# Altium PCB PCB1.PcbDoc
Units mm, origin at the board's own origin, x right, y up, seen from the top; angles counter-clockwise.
Board outline 300 x 100 mm, 2 copper layers (Top Layer, Bottom Layer); 435 components, 0 nets, 870 pads, 0 vias.
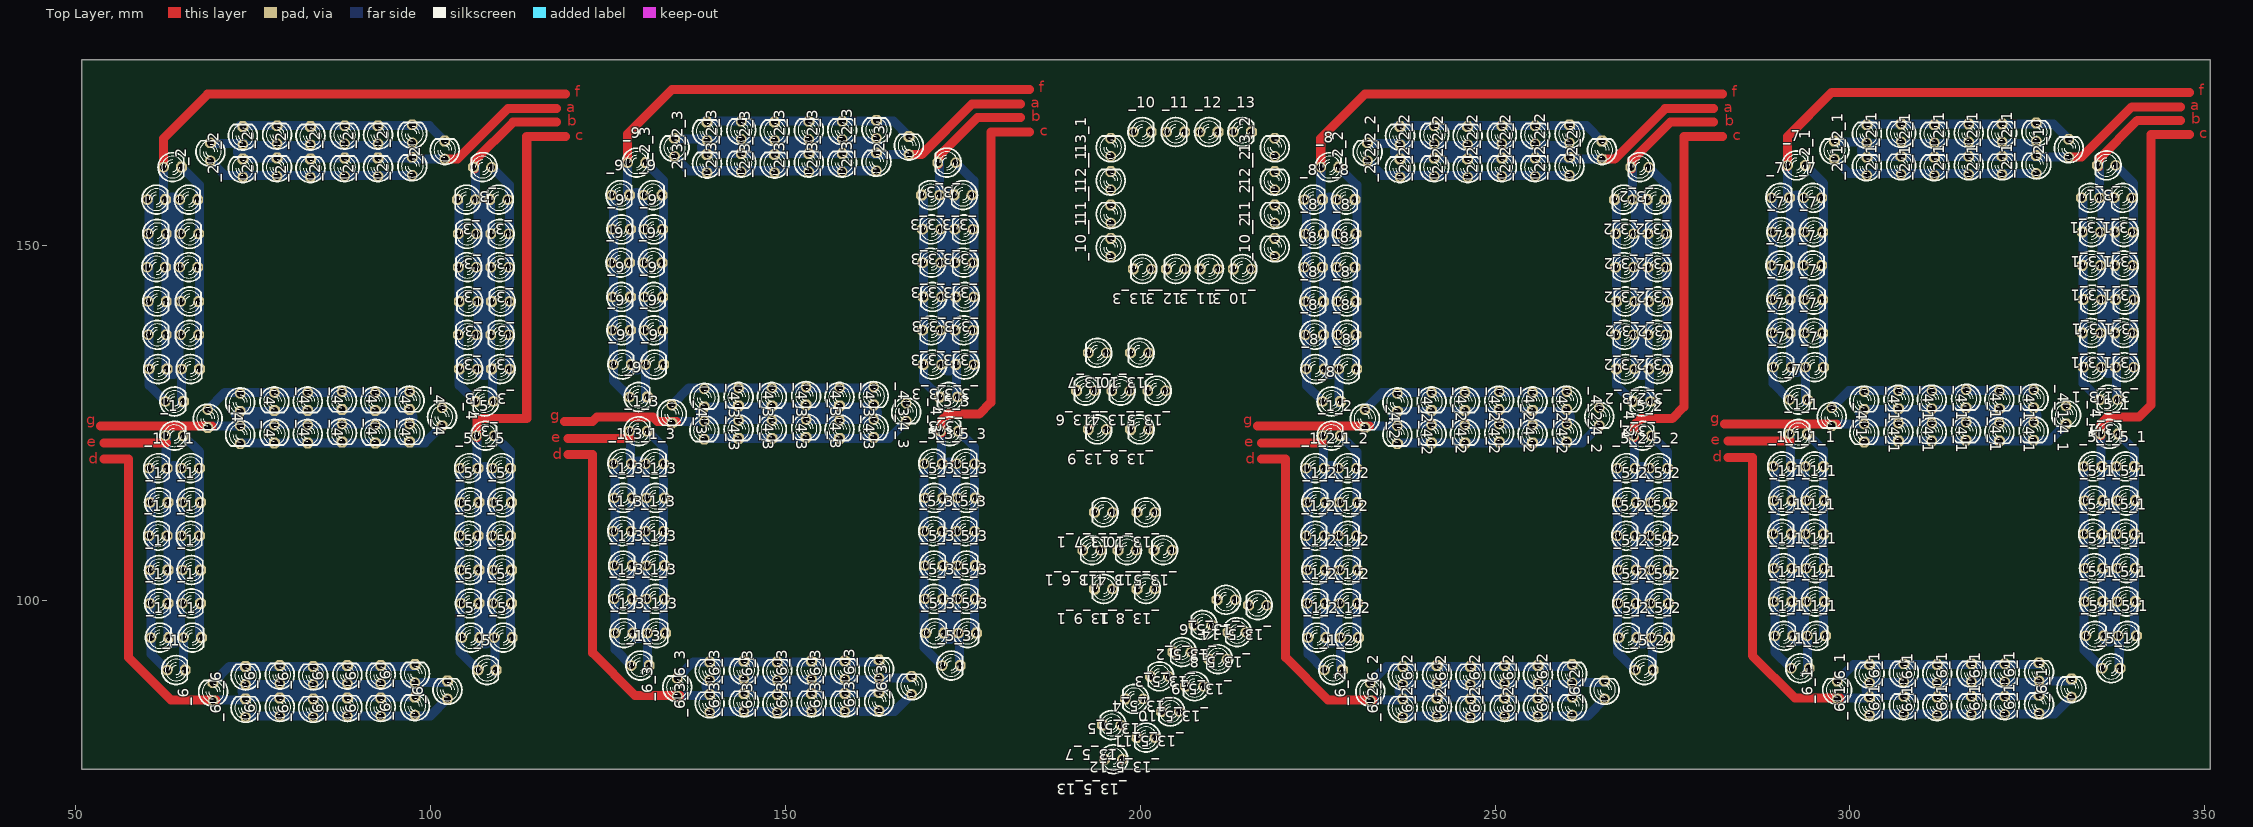
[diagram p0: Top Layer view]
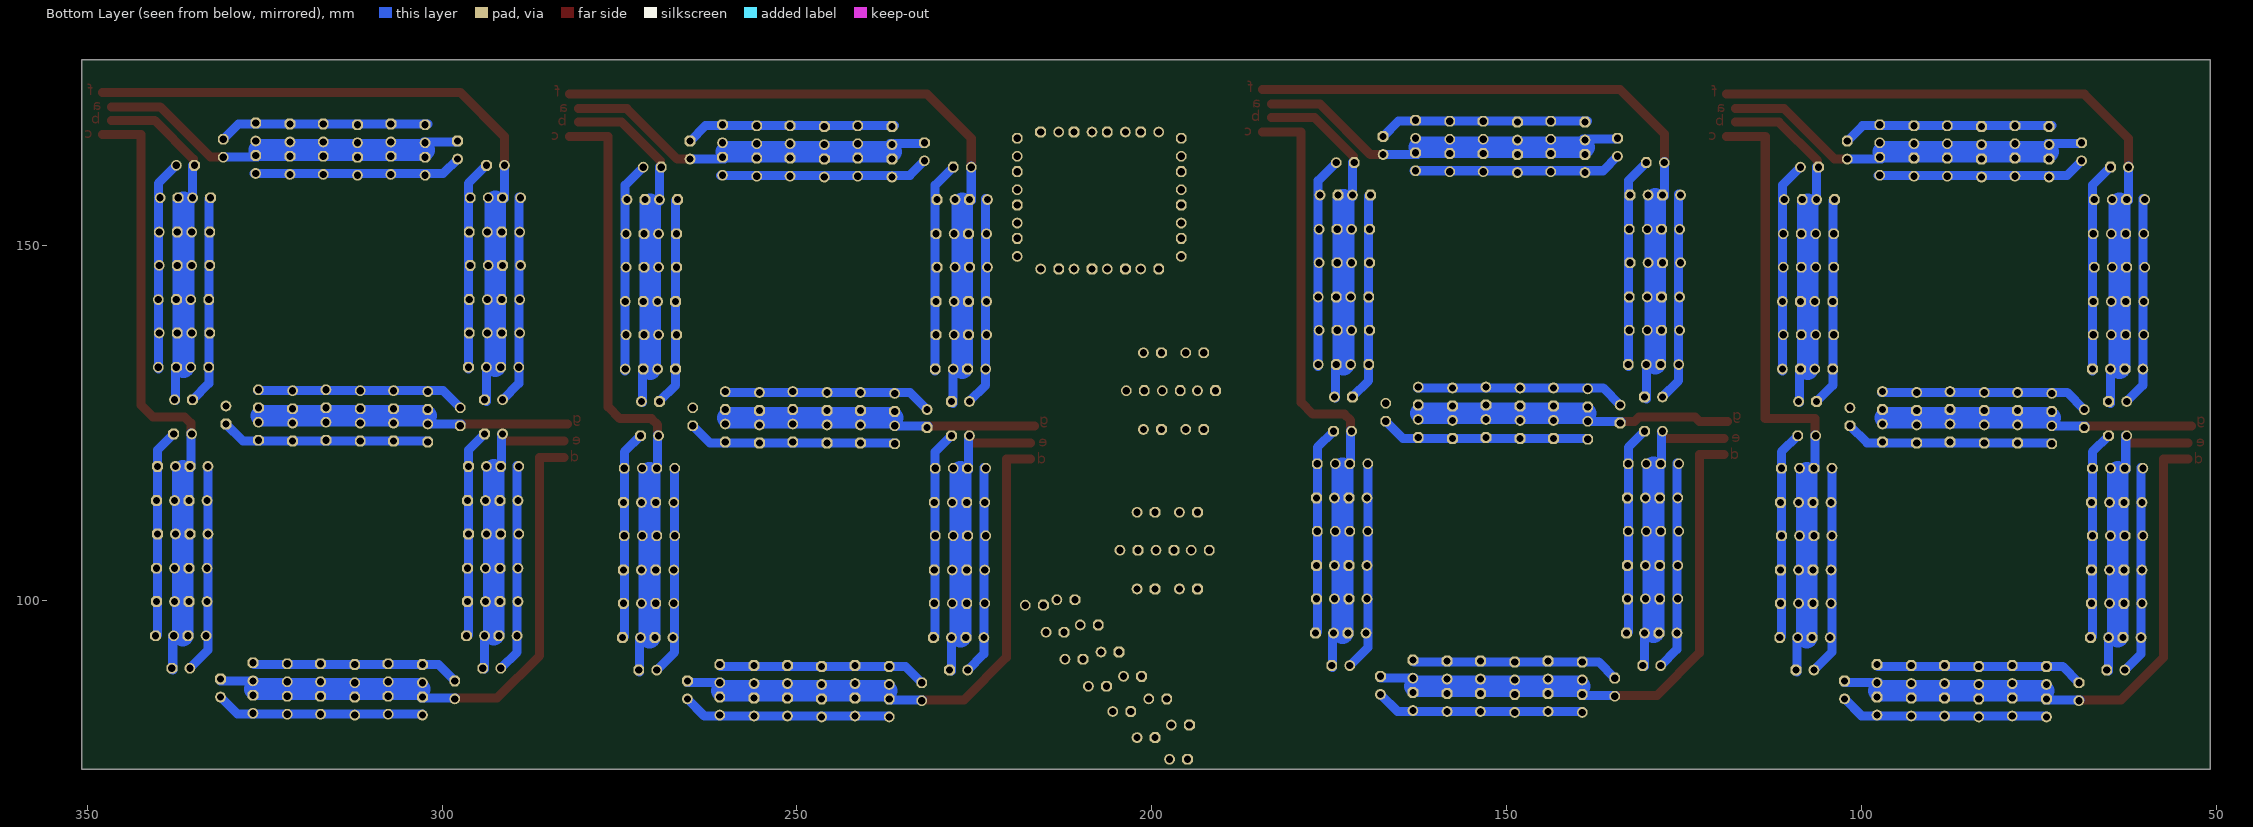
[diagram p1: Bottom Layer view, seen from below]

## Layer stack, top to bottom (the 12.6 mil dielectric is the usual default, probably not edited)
Top Layer: signal copper 0.0356
Dielectric: dielectric 0.32, FR-4, Dk 4.8
Bottom Layer: signal copper 0.0356

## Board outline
50.8,76.2 350.8,76.2 350.8,176.2 50.8,176.2

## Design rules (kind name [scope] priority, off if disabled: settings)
Clearance [All] p1: gap=0.2
PolygonConnect [All] p1: connectstyle=Relief reliefconductorwidth=0.254 reliefentries=4 polygonreliefangle="90 Angle"
RoutingVias [All] p1: holewidth=0.6 width=1 viastyle="Through Hole" minholewidth=0.711 minwidth=1.27 maxholewidth=0.711 maxwidth=1.27
SilkscreenOverComponentPads [All] p1: minsilkscreentomaskgap=0.254
SolderMaskExpansion [All] p1: expansion=0.102
Width [All] p1: maxlimit=0.2 minlimit=0.2 preferedwidth=0.2
27 further rules are at their usual default settings.

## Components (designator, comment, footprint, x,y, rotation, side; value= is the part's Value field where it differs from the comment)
_1 "Comment" My_LED3MM 61.595,118.618 r0 top
_1 "Comment" My_LED3MM 66.167,118.618 r0 top
_1 "Comment" My_LED3MM 61.722,113.792 r0 top
_1 "Comment" My_LED3MM 66.294,113.792 r0 top
_1 "Comment" My_LED3MM 66.294,104.267 r0 top
_1 "Comment" My_LED3MM 61.722,104.267 r0 top
_1 "Comment" My_LED3MM 66.167,109.093 r0 top
_1 "Comment" My_LED3MM 61.595,109.093 r0 top
_1 "Comment" My_LED3MM 66.421,94.742 r0 top
_1 "Comment" My_LED3MM 61.849,94.742 r0 top
_1 "Comment" My_LED3MM 66.294,99.568 r0 top
_1 "Comment" My_LED3MM 61.722,99.568 r0 top
_1 "Comment" My_LED3MM 63.881,123.19 r0 top
_1 "Comment" My_LED3MM 64.135,90.17 r0 top
_1_1 "Comment" My_LED3MM 290.449,118.872 r0 top
_1_1 "Comment" My_LED3MM 295.021,118.872 r0 top
_1_1 "Comment" My_LED3MM 290.576,114.046 r0 top
_1_1 "Comment" My_LED3MM 295.148,114.046 r0 top
_1_1 "Comment" My_LED3MM 295.148,104.521 r0 top
_1_1 "Comment" My_LED3MM 290.576,104.521 r0 top
_1_1 "Comment" My_LED3MM 295.021,109.347 r0 top
_1_1 "Comment" My_LED3MM 290.449,109.347 r0 top
_1_1 "Comment" My_LED3MM 295.275,94.996 r0 top
_1_1 "Comment" My_LED3MM 290.703,94.996 r0 top
_1_1 "Comment" My_LED3MM 295.148,99.822 r0 top
_1_1 "Comment" My_LED3MM 290.576,99.822 r0 top
_1_1 "Comment" My_LED3MM 292.735,123.444 r0 top
_1_1 "Comment" My_LED3MM 292.989,90.424 r0 top
_1_2 "Comment" My_LED3MM 224.663,118.618 r0 top
_1_2 "Comment" My_LED3MM 229.235,118.618 r0 top
_1_2 "Comment" My_LED3MM 224.79,113.792 r0 top
_1_2 "Comment" My_LED3MM 229.362,113.792 r0 top
_1_2 "Comment" My_LED3MM 229.362,104.267 r0 top
_1_2 "Comment" My_LED3MM 224.79,104.267 r0 top
_1_2 "Comment" My_LED3MM 229.235,109.093 r0 top
_1_2 "Comment" My_LED3MM 224.663,109.093 r0 top
_1_2 "Comment" My_LED3MM 229.489,94.742 r0 top
_1_2 "Comment" My_LED3MM 224.917,94.742 r0 top
_1_2 "Comment" My_LED3MM 229.362,99.568 r0 top
_1_2 "Comment" My_LED3MM 224.79,99.568 r0 top
_1_2 "Comment" My_LED3MM 226.949,123.19 r0 top
_1_2 "Comment" My_LED3MM 227.203,90.17 r0 top
_1_3 "Comment" My_LED3MM 127,119.253 r0 top
_1_3 "Comment" My_LED3MM 131.572,119.253 r0 top
_1_3 "Comment" My_LED3MM 127.127,114.427 r0 top
_1_3 "Comment" My_LED3MM 131.699,114.427 r0 top
_1_3 "Comment" My_LED3MM 131.699,104.902 r0 top
_1_3 "Comment" My_LED3MM 127.127,104.902 r0 top
_1_3 "Comment" My_LED3MM 131.572,109.728 r0 top
_1_3 "Comment" My_LED3MM 127,109.728 r0 top
_1_3 "Comment" My_LED3MM 131.826,95.377 r0 top
_1_3 "Comment" My_LED3MM 127.254,95.377 r0 top
_1_3 "Comment" My_LED3MM 131.699,100.203 r0 top
_1_3 "Comment" My_LED3MM 127.127,100.203 r0 top
_1_3 "Comment" My_LED3MM 129.286,123.825 r0 top
_1_3 "Comment" My_LED3MM 129.54,90.805 r0 top
_2 "Comment" My_LED3MM 73.533,160.909 r90 top
_2 "Comment" My_LED3MM 73.533,165.481 r90 top
_2 "Comment" My_LED3MM 78.359,161.036 r90 top
_2 "Comment" My_LED3MM 78.359,165.608 r90 top
_2 "Comment" My_LED3MM 87.884,165.608 r90 top
_2 "Comment" My_LED3MM 87.884,161.036 r90 top
_2 "Comment" My_LED3MM 83.058,165.481 r90 top
_2 "Comment" My_LED3MM 83.058,160.909 r90 top
_2 "Comment" My_LED3MM 97.409,165.735 r90 top
_2 "Comment" My_LED3MM 97.409,161.163 r90 top
_2 "Comment" My_LED3MM 92.583,165.608 r90 top
_2 "Comment" My_LED3MM 92.583,161.036 r90 top
_2 "Comment" My_LED3MM 68.961,163.195 r90 top
_2 "Comment" My_LED3MM 101.981,163.449 r90 top
_2_1 "Comment" My_LED3MM 302.387,161.163 r90 top
_2_1 "Comment" My_LED3MM 302.387,165.735 r90 top
_2_1 "Comment" My_LED3MM 307.213,161.29 r90 top
_2_1 "Comment" My_LED3MM 307.213,165.862 r90 top
_2_1 "Comment" My_LED3MM 316.738,165.862 r90 top
_2_1 "Comment" My_LED3MM 316.738,161.29 r90 top
_2_1 "Comment" My_LED3MM 311.912,165.735 r90 top
_2_1 "Comment" My_LED3MM 311.912,161.163 r90 top
_2_1 "Comment" My_LED3MM 326.263,165.989 r90 top
_2_1 "Comment" My_LED3MM 326.263,161.417 r90 top
_2_1 "Comment" My_LED3MM 321.437,165.862 r90 top
_2_1 "Comment" My_LED3MM 321.437,161.29 r90 top
_2_1 "Comment" My_LED3MM 297.815,163.449 r90 top
_2_1 "Comment" My_LED3MM 330.835,163.703 r90 top
_2_2 "Comment" My_LED3MM 236.601,160.909 r90 top
_2_2 "Comment" My_LED3MM 236.601,165.481 r90 top
_2_2 "Comment" My_LED3MM 241.427,161.036 r90 top
_2_2 "Comment" My_LED3MM 241.427,165.608 r90 top
_2_2 "Comment" My_LED3MM 250.952,165.608 r90 top
_2_2 "Comment" My_LED3MM 250.952,161.036 r90 top
_2_2 "Comment" My_LED3MM 246.126,165.481 r90 top
_2_2 "Comment" My_LED3MM 246.126,160.909 r90 top
_2_2 "Comment" My_LED3MM 260.477,165.735 r90 top
_2_2 "Comment" My_LED3MM 260.477,161.163 r90 top
_2_2 "Comment" My_LED3MM 255.651,165.608 r90 top
_2_2 "Comment" My_LED3MM 255.651,161.036 r90 top
_2_2 "Comment" My_LED3MM 232.029,163.195 r90 top
_2_2 "Comment" My_LED3MM 265.049,163.449 r90 top
_2_3 "Comment" My_LED3MM 138.938,161.544 r90 top
_2_3 "Comment" My_LED3MM 138.938,166.116 r90 top
_2_3 "Comment" My_LED3MM 143.764,161.671 r90 top
_2_3 "Comment" My_LED3MM 143.764,166.243 r90 top
_2_3 "Comment" My_LED3MM 153.289,166.243 r90 top
_2_3 "Comment" My_LED3MM 153.289,161.671 r90 top
_2_3 "Comment" My_LED3MM 148.463,166.116 r90 top
_2_3 "Comment" My_LED3MM 148.463,161.544 r90 top
_2_3 "Comment" My_LED3MM 162.814,166.37 r90 top
_2_3 "Comment" My_LED3MM 162.814,161.798 r90 top
_2_3 "Comment" My_LED3MM 157.988,166.243 r90 top
_2_3 "Comment" My_LED3MM 157.988,161.671 r90 top
_2_3 "Comment" My_LED3MM 134.366,163.83 r90 top
_2_3 "Comment" My_LED3MM 167.386,164.084 r90 top
_3 "Comment" My_LED3MM 109.855,132.588 r180 top
_3 "Comment" My_LED3MM 105.283,132.588 r180 top
_3 "Comment" My_LED3MM 109.728,137.414 r180 top
_3 "Comment" My_LED3MM 105.156,137.414 r180 top
_3 "Comment" My_LED3MM 105.156,146.939 r180 top
_3 "Comment" My_LED3MM 109.728,146.939 r180 top
_3 "Comment" My_LED3MM 105.283,142.113 r180 top
_3 "Comment" My_LED3MM 109.855,142.113 r180 top
_3 "Comment" My_LED3MM 105.029,156.464 r180 top
_3 "Comment" My_LED3MM 109.601,156.464 r180 top
_3 "Comment" My_LED3MM 105.156,151.638 r180 top
_3 "Comment" My_LED3MM 109.728,151.638 r180 top
_3 "Comment" My_LED3MM 107.569,128.016 r180 top
_3 "Comment" My_LED3MM 107.315,161.036 r180 top
_3_1 "Comment" My_LED3MM 338.709,132.842 r180 top
_3_1 "Comment" My_LED3MM 334.137,132.842 r180 top
_3_1 "Comment" My_LED3MM 338.582,137.668 r180 top
_3_1 "Comment" My_LED3MM 334.01,137.668 r180 top
_3_1 "Comment" My_LED3MM 334.01,147.193 r180 top
_3_1 "Comment" My_LED3MM 338.582,147.193 r180 top
_3_1 "Comment" My_LED3MM 334.137,142.367 r180 top
_3_1 "Comment" My_LED3MM 338.709,142.367 r180 top
_3_1 "Comment" My_LED3MM 333.883,156.718 r180 top
_3_1 "Comment" My_LED3MM 338.455,156.718 r180 top
_3_1 "Comment" My_LED3MM 334.01,151.892 r180 top
_3_1 "Comment" My_LED3MM 338.582,151.892 r180 top
_3_1 "Comment" My_LED3MM 336.423,128.27 r180 top
_3_1 "Comment" My_LED3MM 336.169,161.29 r180 top
_3_2 "Comment" My_LED3MM 272.923,132.588 r180 top
_3_2 "Comment" My_LED3MM 268.351,132.588 r180 top
_3_2 "Comment" My_LED3MM 272.796,137.414 r180 top
_3_2 "Comment" My_LED3MM 268.224,137.414 r180 top
_3_2 "Comment" My_LED3MM 268.224,146.939 r180 top
_3_2 "Comment" My_LED3MM 272.796,146.939 r180 top
_3_2 "Comment" My_LED3MM 268.351,142.113 r180 top
_3_2 "Comment" My_LED3MM 272.923,142.113 r180 top
_3_2 "Comment" My_LED3MM 268.097,156.464 r180 top
_3_2 "Comment" My_LED3MM 272.669,156.464 r180 top
_3_2 "Comment" My_LED3MM 268.224,151.638 r180 top
_3_2 "Comment" My_LED3MM 272.796,151.638 r180 top
_3_2 "Comment" My_LED3MM 270.637,128.016 r180 top
_3_2 "Comment" My_LED3MM 270.383,161.036 r180 top
_3_3 "Comment" My_LED3MM 175.26,133.223 r180 top
_3_3 "Comment" My_LED3MM 170.688,133.223 r180 top
_3_3 "Comment" My_LED3MM 175.133,138.049 r180 top
_3_3 "Comment" My_LED3MM 170.561,138.049 r180 top
_3_3 "Comment" My_LED3MM 170.561,147.574 r180 top
_3_3 "Comment" My_LED3MM 175.133,147.574 r180 top
_3_3 "Comment" My_LED3MM 170.688,142.748 r180 top
_3_3 "Comment" My_LED3MM 175.26,142.748 r180 top
_3_3 "Comment" My_LED3MM 170.434,157.099 r180 top
_3_3 "Comment" My_LED3MM 175.006,157.099 r180 top
_3_3 "Comment" My_LED3MM 170.561,152.273 r180 top
_3_3 "Comment" My_LED3MM 175.133,152.273 r180 top
_3_3 "Comment" My_LED3MM 172.974,128.651 r180 top
_3_3 "Comment" My_LED3MM 172.72,161.671 r180 top
_4 "Comment" My_LED3MM 97.028,128.143 r270 top
_4 "Comment" My_LED3MM 97.028,123.571 r270 top
_4 "Comment" My_LED3MM 92.202,128.016 r270 top
_4 "Comment" My_LED3MM 92.202,123.444 r270 top
_4 "Comment" My_LED3MM 82.677,123.444 r270 top
_4 "Comment" My_LED3MM 82.677,128.016 r270 top
_4 "Comment" My_LED3MM 87.503,123.571 r270 top
_4 "Comment" My_LED3MM 87.503,128.143 r270 top
_4 "Comment" My_LED3MM 73.152,123.317 r270 top
_4 "Comment" My_LED3MM 73.152,127.889 r270 top
_4 "Comment" My_LED3MM 77.978,123.444 r270 top
_4 "Comment" My_LED3MM 77.978,128.016 r270 top
_4 "Comment" My_LED3MM 101.6,125.857 r270 top
_4 "Comment" My_LED3MM 68.58,125.603 r270 top
_4_1 "Comment" My_LED3MM 325.882,128.397 r270 top
_4_1 "Comment" My_LED3MM 325.882,123.825 r270 top
_4_1 "Comment" My_LED3MM 321.056,128.27 r270 top
_4_1 "Comment" My_LED3MM 321.056,123.698 r270 top
_4_1 "Comment" My_LED3MM 311.531,123.698 r270 top
_4_1 "Comment" My_LED3MM 311.531,128.27 r270 top
_4_1 "Comment" My_LED3MM 316.357,123.825 r270 top
_4_1 "Comment" My_LED3MM 316.357,128.397 r270 top
_4_1 "Comment" My_LED3MM 302.006,123.571 r270 top
_4_1 "Comment" My_LED3MM 302.006,128.143 r270 top
_4_1 "Comment" My_LED3MM 306.832,123.698 r270 top
_4_1 "Comment" My_LED3MM 306.832,128.27 r270 top
_4_1 "Comment" My_LED3MM 330.454,126.111 r270 top
_4_1 "Comment" My_LED3MM 297.434,125.857 r270 top
_4_2 "Comment" My_LED3MM 260.096,128.143 r270 top
_4_2 "Comment" My_LED3MM 260.096,123.571 r270 top
_4_2 "Comment" My_LED3MM 255.27,128.016 r270 top
_4_2 "Comment" My_LED3MM 255.27,123.444 r270 top
_4_2 "Comment" My_LED3MM 245.745,123.444 r270 top
_4_2 "Comment" My_LED3MM 245.745,128.016 r270 top
_4_2 "Comment" My_LED3MM 250.571,123.571 r270 top
_4_2 "Comment" My_LED3MM 250.571,128.143 r270 top
_4_2 "Comment" My_LED3MM 236.22,123.317 r270 top
_4_2 "Comment" My_LED3MM 236.22,127.889 r270 top
_4_2 "Comment" My_LED3MM 241.046,123.444 r270 top
_4_2 "Comment" My_LED3MM 241.046,128.016 r270 top
_4_2 "Comment" My_LED3MM 264.668,125.857 r270 top
_4_2 "Comment" My_LED3MM 231.648,125.603 r270 top
_4_3 "Comment" My_LED3MM 162.433,128.778 r270 top
_4_3 "Comment" My_LED3MM 162.433,124.206 r270 top
_4_3 "Comment" My_LED3MM 157.607,128.651 r270 top
_4_3 "Comment" My_LED3MM 157.607,124.079 r270 top
_4_3 "Comment" My_LED3MM 148.082,124.079 r270 top
_4_3 "Comment" My_LED3MM 148.082,128.651 r270 top
_4_3 "Comment" My_LED3MM 152.908,124.206 r270 top
_4_3 "Comment" My_LED3MM 152.908,128.778 r270 top
_4_3 "Comment" My_LED3MM 138.557,123.952 r270 top
_4_3 "Comment" My_LED3MM 138.557,128.524 r270 top
_4_3 "Comment" My_LED3MM 143.383,124.079 r270 top
_4_3 "Comment" My_LED3MM 143.383,128.651 r270 top
_4_3 "Comment" My_LED3MM 167.005,126.492 r270 top
_4_3 "Comment" My_LED3MM 133.985,126.238 r270 top
_5 "Comment" My_LED3MM 105.41,118.618 r0 top
_5 "Comment" My_LED3MM 109.982,118.618 r0 top
_5 "Comment" My_LED3MM 105.537,113.792 r0 top
_5 "Comment" My_LED3MM 110.109,113.792 r0 top
_5 "Comment" My_LED3MM 110.109,104.267 r0 top
_5 "Comment" My_LED3MM 105.537,104.267 r0 top
_5 "Comment" My_LED3MM 109.982,109.093 r0 top
_5 "Comment" My_LED3MM 105.41,109.093 r0 top
_5 "Comment" My_LED3MM 110.236,94.742 r0 top
_5 "Comment" My_LED3MM 105.664,94.742 r0 top
_5 "Comment" My_LED3MM 110.109,99.568 r0 top
_5 "Comment" My_LED3MM 105.537,99.568 r0 top
_5 "Comment" My_LED3MM 107.696,123.19 r0 top
_5 "Comment" My_LED3MM 107.95,90.17 r0 top
_5_1 "Comment" My_LED3MM 334.264,118.872 r0 top
_5_1 "Comment" My_LED3MM 338.836,118.872 r0 top
_5_1 "Comment" My_LED3MM 334.391,114.046 r0 top
_5_1 "Comment" My_LED3MM 338.963,114.046 r0 top
_5_1 "Comment" My_LED3MM 338.963,104.521 r0 top
_5_1 "Comment" My_LED3MM 334.391,104.521 r0 top
_5_1 "Comment" My_LED3MM 338.836,109.347 r0 top
_5_1 "Comment" My_LED3MM 334.264,109.347 r0 top
_5_1 "Comment" My_LED3MM 339.09,94.996 r0 top
_5_1 "Comment" My_LED3MM 334.518,94.996 r0 top
_5_1 "Comment" My_LED3MM 338.963,99.822 r0 top
_5_1 "Comment" My_LED3MM 334.391,99.822 r0 top
_5_1 "Comment" My_LED3MM 336.55,123.444 r0 top
_5_1 "Comment" My_LED3MM 336.804,90.424 r0 top
_5_2 "Comment" My_LED3MM 268.478,118.618 r0 top
_5_2 "Comment" My_LED3MM 273.05,118.618 r0 top
_5_2 "Comment" My_LED3MM 268.605,113.792 r0 top
_5_2 "Comment" My_LED3MM 273.177,113.792 r0 top
_5_2 "Comment" My_LED3MM 273.177,104.267 r0 top
_5_2 "Comment" My_LED3MM 268.605,104.267 r0 top
_5_2 "Comment" My_LED3MM 273.05,109.093 r0 top
_5_2 "Comment" My_LED3MM 268.478,109.093 r0 top
_5_2 "Comment" My_LED3MM 273.304,94.742 r0 top
_5_2 "Comment" My_LED3MM 268.732,94.742 r0 top
_5_2 "Comment" My_LED3MM 273.177,99.568 r0 top
_5_2 "Comment" My_LED3MM 268.605,99.568 r0 top
_5_2 "Comment" My_LED3MM 270.764,123.19 r0 top
_5_2 "Comment" My_LED3MM 271.018,90.17 r0 top
_5_3 "Comment" My_LED3MM 170.815,119.253 r0 top
_5_3 "Comment" My_LED3MM 175.387,119.253 r0 top
_5_3 "Comment" My_LED3MM 170.942,114.427 r0 top
_5_3 "Comment" My_LED3MM 175.514,114.427 r0 top
_5_3 "Comment" My_LED3MM 175.514,104.902 r0 top
_5_3 "Comment" My_LED3MM 170.942,104.902 r0 top
_5_3 "Comment" My_LED3MM 175.387,109.728 r0 top
_5_3 "Comment" My_LED3MM 170.815,109.728 r0 top
_5_3 "Comment" My_LED3MM 175.641,95.377 r0 top
_5_3 "Comment" My_LED3MM 171.069,95.377 r0 top
_5_3 "Comment" My_LED3MM 175.514,100.203 r0 top
_5_3 "Comment" My_LED3MM 170.942,100.203 r0 top
_5_3 "Comment" My_LED3MM 173.101,123.825 r0 top
_5_3 "Comment" My_LED3MM 173.355,90.805 r0 top
_6 "Comment" My_LED3MM 73.914,84.836 r90 top
_6 "Comment" My_LED3MM 73.914,89.408 r90 top
_6 "Comment" My_LED3MM 78.74,84.963 r90 top
_6 "Comment" My_LED3MM 78.74,89.535 r90 top
_6 "Comment" My_LED3MM 88.265,89.535 r90 top
_6 "Comment" My_LED3MM 88.265,84.963 r90 top
_6 "Comment" My_LED3MM 83.439,89.408 r90 top
_6 "Comment" My_LED3MM 83.439,84.836 r90 top
_6 "Comment" My_LED3MM 97.79,89.662 r90 top
_6 "Comment" My_LED3MM 97.79,85.09 r90 top
_6 "Comment" My_LED3MM 92.964,89.535 r90 top
_6 "Comment" My_LED3MM 92.964,84.963 r90 top
_6 "Comment" My_LED3MM 69.342,87.122 r90 top
_6 "Comment" My_LED3MM 102.362,87.376 r90 top
_6_1 "Comment" My_LED3MM 302.768,85.09 r90 top
_6_1 "Comment" My_LED3MM 302.768,89.662 r90 top
_6_1 "Comment" My_LED3MM 307.594,85.217 r90 top
_6_1 "Comment" My_LED3MM 307.594,89.789 r90 top
_6_1 "Comment" My_LED3MM 317.119,89.789 r90 top
_6_1 "Comment" My_LED3MM 317.119,85.217 r90 top
_6_1 "Comment" My_LED3MM 312.293,89.662 r90 top
_6_1 "Comment" My_LED3MM 312.293,85.09 r90 top
_6_1 "Comment" My_LED3MM 326.644,89.916 r90 top
_6_1 "Comment" My_LED3MM 326.644,85.344 r90 top
_6_1 "Comment" My_LED3MM 321.818,89.789 r90 top
_6_1 "Comment" My_LED3MM 321.818,85.217 r90 top
_6_1 "Comment" My_LED3MM 298.196,87.376 r90 top
_6_1 "Comment" My_LED3MM 331.216,87.63 r90 top
_6_2 "Comment" My_LED3MM 236.982,84.836 r90 top
_6_2 "Comment" My_LED3MM 236.982,89.408 r90 top
_6_2 "Comment" My_LED3MM 241.808,84.963 r90 top
_6_2 "Comment" My_LED3MM 241.808,89.535 r90 top
_6_2 "Comment" My_LED3MM 251.333,89.535 r90 top
_6_2 "Comment" My_LED3MM 251.333,84.963 r90 top
_6_2 "Comment" My_LED3MM 246.507,89.408 r90 top
_6_2 "Comment" My_LED3MM 246.507,84.836 r90 top
_6_2 "Comment" My_LED3MM 260.858,89.662 r90 top
_6_2 "Comment" My_LED3MM 260.858,85.09 r90 top
_6_2 "Comment" My_LED3MM 256.032,89.535 r90 top
_6_2 "Comment" My_LED3MM 256.032,84.963 r90 top
_6_2 "Comment" My_LED3MM 232.41,87.122 r90 top
_6_2 "Comment" My_LED3MM 265.43,87.376 r90 top
_6_3 "Comment" My_LED3MM 139.319,85.471 r90 top
_6_3 "Comment" My_LED3MM 139.319,90.043 r90 top
_6_3 "Comment" My_LED3MM 144.145,85.598 r90 top
_6_3 "Comment" My_LED3MM 144.145,90.17 r90 top
_6_3 "Comment" My_LED3MM 153.67,90.17 r90 top
_6_3 "Comment" My_LED3MM 153.67,85.598 r90 top
_6_3 "Comment" My_LED3MM 148.844,90.043 r90 top
_6_3 "Comment" My_LED3MM 148.844,85.471 r90 top
_6_3 "Comment" My_LED3MM 163.195,90.297 r90 top
_6_3 "Comment" My_LED3MM 163.195,85.725 r90 top
_6_3 "Comment" My_LED3MM 158.369,90.17 r90 top
_6_3 "Comment" My_LED3MM 158.369,85.598 r90 top
_6_3 "Comment" My_LED3MM 134.747,87.757 r90 top
_6_3 "Comment" My_LED3MM 167.767,88.011 r90 top
_7 "Comment" My_LED3MM 292.735,128.27 r0 top
_7 "Comment" My_LED3MM 292.481,161.29 r0 top
_7 "Comment" My_LED3MM 290.322,137.668 r0 top
_7 "Comment" My_LED3MM 294.894,137.668 r0 top
_7 "Comment" My_LED3MM 290.449,132.842 r0 top
_7 "Comment" My_LED3MM 295.021,132.842 r0 top
_7 "Comment" My_LED3MM 290.195,147.193 r0 top
_7 "Comment" My_LED3MM 294.767,147.193 r0 top
_7 "Comment" My_LED3MM 290.322,142.367 r0 top
_7 "Comment" My_LED3MM 294.894,142.367 r0 top
_7 "Comment" My_LED3MM 294.894,151.892 r0 top
_7 "Comment" My_LED3MM 290.322,151.892 r0 top
_7 "Comment" My_LED3MM 294.767,156.718 r0 top
_7 "Comment" My_LED3MM 290.195,156.718 r0 top
_8 "Comment" My_LED3MM 226.949,128.016 r0 top
_8 "Comment" My_LED3MM 226.695,161.036 r0 top
_8 "Comment" My_LED3MM 224.536,137.414 r0 top
_8 "Comment" My_LED3MM 229.108,137.414 r0 top
_8 "Comment" My_LED3MM 224.663,132.588 r0 top
_8 "Comment" My_LED3MM 229.235,132.588 r0 top
_8 "Comment" My_LED3MM 224.409,146.939 r0 top
_8 "Comment" My_LED3MM 228.981,146.939 r0 top
_8 "Comment" My_LED3MM 224.536,142.113 r0 top
_8 "Comment" My_LED3MM 229.108,142.113 r0 top
_8 "Comment" My_LED3MM 229.108,151.638 r0 top
_8 "Comment" My_LED3MM 224.536,151.638 r0 top
_8 "Comment" My_LED3MM 228.981,156.464 r0 top
_8 "Comment" My_LED3MM 224.409,156.464 r0 top
_9 "Comment" My_LED3MM 129.286,128.651 r0 top
_9 "Comment" My_LED3MM 129.032,161.671 r0 top
_9 "Comment" My_LED3MM 126.873,138.049 r0 top
_9 "Comment" My_LED3MM 131.445,138.049 r0 top
_9 "Comment" My_LED3MM 127,133.223 r0 top
_9 "Comment" My_LED3MM 131.572,133.223 r0 top
_9 "Comment" My_LED3MM 126.746,147.574 r0 top
_9 "Comment" My_LED3MM 131.318,147.574 r0 top
_9 "Comment" My_LED3MM 126.873,142.748 r0 top
_9 "Comment" My_LED3MM 131.445,142.748 r0 top
_9 "Comment" My_LED3MM 131.445,152.273 r0 top
_9 "Comment" My_LED3MM 126.873,152.273 r0 top
_9 "Comment" My_LED3MM 131.318,157.099 r0 top
_9 "Comment" My_LED3MM 126.746,157.099 r0 top
_10 "Comment" My_LED3MM 200.279,165.989 r0 top
_10_1 "Comment" My_LED3MM 195.834,149.733 r90 top
_10_2 "Comment" My_LED3MM 218.948,149.733 r90 top
_10_3 "Comment" My_LED3MM 214.376,146.685 r180 top
_11 "Comment" My_LED3MM 204.978,165.989 r0 top
_11_1 "Comment" My_LED3MM 195.834,154.432 r90 top
_11_2 "Comment" My_LED3MM 218.948,154.432 r90 top
_11_3 "Comment" My_LED3MM 209.677,146.685 r180 top
_12 "Comment" My_LED3MM 209.677,165.989 r0 top
_12_1 "Comment" My_LED3MM 195.834,159.131 r90 top
_12_2 "Comment" My_LED3MM 218.948,159.131 r90 top
_12_3 "Comment" My_LED3MM 204.978,146.685 r180 top
_13 "Comment" My_LED3MM 214.376,165.989 r0 top
_13_1 "Comment" My_LED3MM 195.834,163.83 r90 top
_13_2 "Comment" My_LED3MM 218.948,163.83 r90 top
_13_3 "Comment" My_LED3MM 200.279,146.685 r180 top
_13_4 "Comment" My_LED3MM 197.231,129.54 r180 top
_13_4_1 "Comment" My_LED3MM 198.12,107.061 r180 top
_13_5 "Comment" My_LED3MM 202.311,129.54 r180 top
_13_5_1 "Comment" My_LED3MM 203.2,107.061 r180 top
_13_5_2 "Comment" My_LED3MM 208.788,96.52 r180 top
_13_5_3 "Comment" My_LED3MM 205.867,92.71 r180 top
_13_5_4 "Comment" My_LED3MM 202.692,89.281 r180 top
_13_5_5 "Comment" My_LED3MM 199.136,86.106 r180 top
_13_5_6 "Comment" My_LED3MM 212.09,100.076 r180 top
_13_5_7 "Comment" My_LED3MM 195.961,82.423 r180 top
_13_5_8 "Comment" My_LED3MM 213.614,95.504 r180 top
_13_5_9 "Comment" My_LED3MM 210.947,91.694 r180 top
_13_5_10 "Comment" My_LED3MM 207.645,87.884 r180 top
_13_5_11 "Comment" My_LED3MM 204.216,84.328 r180 top
_13_5_12 "Comment" My_LED3MM 200.787,80.645 r180 top
_13_5_13 "Comment" My_LED3MM 196.215,77.597 r180 top
_13_5_14 "Comment" My_LED3MM 216.535,99.314 r180 top
_13_6 "Comment" My_LED3MM 192.278,129.54 r180 top
_13_6_1 "Comment" My_LED3MM 193.167,107.061 r180 top
_13_7 "Comment" My_LED3MM 193.929,134.874 r180 top
_13_7_1 "Comment" My_LED3MM 194.818,112.395 r180 top
_13_8 "Comment" My_LED3MM 199.898,124.079 r180 top
_13_8_1 "Comment" My_LED3MM 200.787,101.6 r180 top
_13_9 "Comment" My_LED3MM 193.929,124.079 r180 top
_13_9_1 "Comment" My_LED3MM 194.818,101.6 r180 top
_13_10 "Comment" My_LED3MM 199.898,134.874 r180 top
_13_10_1 "Comment" My_LED3MM 200.787,112.395 r180 top
? "Comment" My_LED3MM 63.881,128.016 r0 top
? "Comment" My_LED3MM 63.627,161.036 r0 top
? "Comment" My_LED3MM 61.468,137.414 r0 top
? "Comment" My_LED3MM 66.04,137.414 r0 top
? "Comment" My_LED3MM 61.595,132.588 r0 top
? "Comment" My_LED3MM 66.167,132.588 r0 top
? "Comment" My_LED3MM 61.341,146.939 r0 top
? "Comment" My_LED3MM 65.913,146.939 r0 top
? "Comment" My_LED3MM 61.468,142.113 r0 top
? "Comment" My_LED3MM 66.04,142.113 r0 top
? "Comment" My_LED3MM 66.04,151.638 r0 top
? "Comment" My_LED3MM 61.468,151.638 r0 top
? "Comment" My_LED3MM 65.913,156.464 r0 top
? "Comment" My_LED3MM 61.341,156.464 r0 top

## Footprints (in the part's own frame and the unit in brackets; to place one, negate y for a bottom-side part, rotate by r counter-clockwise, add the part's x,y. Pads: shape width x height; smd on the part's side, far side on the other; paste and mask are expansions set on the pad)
My_LED3MM [mil]
  round 60 hole 40: A(-50,0)
  oct 60x60 hole 40: K(50,0)
  silkscreen extent -80,-80 62,80

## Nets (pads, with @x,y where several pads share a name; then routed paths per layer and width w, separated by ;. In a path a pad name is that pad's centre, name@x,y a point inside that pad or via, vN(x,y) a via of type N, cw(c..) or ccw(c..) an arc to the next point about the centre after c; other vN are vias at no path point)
pads on no net: ?.A ?.K _1.A _1.K _1_1.A _1_1.K _1_2.A _1_2.K _1_3.A _1_3.K _2.A _2.K _2_1.A _2_1.K _2_2.A _2_2.K _2_3.A _2_3.K _3.A _3.K _3_1.A _3_1.K _3_2.A _3_2.K _3_3.A _3_3.K _4.A _4.K _4_1.A _4_1.K _4_2.A _4_2.K _4_3.A _4_3.K _5.A _5.K _5_1.A _5_1.K _5_2.A _5_2.K _5_3.A _5_3.K _6.A _6.K _6_1.A _6_1.K _6_2.A _6_2.K _6_3.A _6_3.K _7.A _7.K _8.A _8.K _9.A _9.K _10.A _10.K _10_1.A _10_1.K _10_2.A _10_2.K _10_3.A _10_3.K _11.A _11.K _11_1.A _11_1.K _11_2.A _11_2.K _11_3.A _11_3.K _12.A _12.K _12_1.A _12_1.K _12_2.A _12_2.K _12_3.A _12_3.K _13.A _13.K _13_1.A _13_1.K _13_2.A _13_2.K _13_3.A _13_3.K _13_4.A _13_4.K _13_4_1.A _13_4_1.K _13_5.A _13_5.K _13_5_1.A _13_5_1.K _13_5_2.A _13_5_2.K _13_5_3.A _13_5_3.K _13_5_4.A _13_5_4.K _13_5_5.A _13_5_5.K _13_5_6.A _13_5_6.K _13_5_7.A _13_5_7.K _13_5_8.A _13_5_8.K _13_5_9.A _13_5_9.K _13_5_10.A _13_5_10.K _13_5_11.A _13_5_11.K _13_5_12.A _13_5_12.K _13_5_13.A _13_5_13.K _13_5_14.A _13_5_14.K _13_6.A _13_6.K _13_6_1.A _13_6_1.K _13_7.A _13_7.K _13_7_1.A _13_7_1.K _13_8.A _13_8.K _13_8_1.A _13_8_1.K _13_9.A _13_9.K _13_9_1.A _13_9_1.K _13_10.A _13_10.K _13_10_1.A _13_10_1.K
copper on no net: | length 3440.6
  Top Layer w1.27: 53.467,124.587 69.215,124.587 ; 53.975,119.888 57.404,119.888 57.404,91.948 63.373,85.979 69.723,85.979 ; 53.975,122.174 62.738,122.174 ; 62.357,160.909 62.357,165.1 68.58,171.323 118.999,171.323 ; 101.981,162.179 103.759,162.179 110.871,169.291 117.729,169.291 ; 106.172,160.782 106.172,161.925 111.633,167.386 117.729,167.386 ; 106.553,122.936 106.553,125.603 113.538,125.603 113.538,165.354 118.999,165.354 ; 118.872,125.222 122.809,125.222 123.444,125.857 130.048,125.857 131.318,125.857 131.953,125.222 134.62,125.222 ; 119.38,120.523 122.809,120.523 122.809,92.583 128.778,86.614 135.128,86.614 ; 119.38,122.809 128.143,122.809 ; 127.762,161.544 127.762,165.735 133.985,171.958 184.404,171.958 ; 167.386,162.814 169.164,162.814 176.276,169.926 183.134,169.926 ; 171.577,161.417 171.577,162.56 177.038,168.021 183.134,168.021 ; 171.958,123.571 171.958,125.349 172.847,126.238 177.292,126.238 178.943,127.889 178.943,165.989 184.404,165.989 ; 216.535,124.587 232.283,124.587 ; 217.043,119.888 220.472,119.888 220.472,91.948 226.441,85.979 232.791,85.979 ; 217.043,122.174 225.806,122.174 ; 225.425,160.909 225.425,165.1 231.648,171.323 282.067,171.323 ; 265.049,162.179 266.827,162.179 273.939,169.291 280.797,169.291 ; 269.24,160.782 269.24,161.925 274.701,167.386 280.797,167.386 ; 269.621,122.936 269.621,124.714 270.51,125.603 274.955,125.603 276.606,127.254 276.606,165.354 282.067,165.354 ; 282.321,124.841 298.069,124.841 ; 282.829,120.142 286.258,120.142 286.258,92.202 292.227,86.233 298.577,86.233 ; 282.829,122.428 291.592,122.428 ; 291.211,161.163 291.211,165.354 297.434,171.577 347.853,171.577 ; 330.835,162.433 332.613,162.433 339.725,169.545 346.583,169.545 ; 335.026,161.036 335.026,162.179 340.487,167.64 346.583,167.64 ; 335.407,123.19 335.407,124.968 336.296,125.857 340.741,125.857 342.392,127.508 342.392,165.608 347.853,165.608
  Bottom Layer w1.27: 60.325,156.591 60.325,130.302 62.611,128.016 ; 60.579,118.745 60.579,92.456 62.865,90.17 ; 62.357,156.337 62.357,161.163 ; 62.738,118.364 62.738,123.19 ; 64.897,127.762 64.897,132.588 ; 64.897,161.036 67.437,158.496 67.437,132.334 ; 65.151,90.043 65.151,94.869 ; 65.151,123.19 67.437,120.904 67.437,94.869 ; 68.453,124.587 73.279,124.587 ; 68.58,126.873 70.993,129.286 97.155,129.286 ; 68.961,161.925 70.993,159.893 97.663,159.893 ; 68.961,164.338 73.787,164.338 ; 69.215,85.979 74.041,85.979 ; 69.342,88.392 71.628,90.678 97.663,90.678 ; 73.025,122.174 99.187,122.174 101.6,124.587 ; 73.152,166.878 99.822,166.878 101.981,164.719 ; 73.914,83.693 99.949,83.693 102.362,86.106 ; 97.155,162.179 101.981,162.179 ; 97.536,88.392 102.362,88.392 ; 104.013,156.337 104.013,130.302 106.299,128.016 ; 104.14,118.745 104.14,92.71 106.68,90.17 ; 106.299,156.21 106.299,161.036 ; 106.553,118.491 106.553,123.317 ; 108.585,161.036 111.125,158.496 111.125,132.334 ; 108.712,127.889 108.712,132.715 ; 108.966,123.19 111.252,120.904 111.252,94.869 ; 109.093,89.916 109.093,94.742 ; 125.73,157.226 125.73,130.937 128.016,128.651 ; 125.984,119.38 125.984,93.091 128.27,90.805 ; 127.762,156.972 127.762,161.798 ; 128.143,118.999 128.143,123.825 ; 130.302,128.397 130.302,133.223 ; 130.302,161.671 132.842,159.131 132.842,132.969 ; 130.556,90.678 130.556,95.504 ; 130.556,123.825 132.842,121.539 132.842,95.504 ; 133.858,125.222 138.684,125.222 ; 133.985,127.508 136.398,129.921 162.56,129.921 ; 134.366,162.56 136.398,160.528 163.068,160.528 ; 134.366,164.973 139.192,164.973 ; 134.62,86.614 139.446,86.614 ; 134.747,89.027 137.033,91.313 163.068,91.313 ; 138.43,122.809 164.592,122.809 167.005,125.222 ; 138.557,167.513 165.227,167.513 167.386,165.354 ; 139.319,84.328 165.354,84.328 167.767,86.741 ; 162.56,162.814 167.386,162.814 ; 162.941,89.027 167.767,89.027 ; 169.418,156.972 169.418,130.937 171.704,128.651 ; 169.545,119.38 169.545,93.345 172.085,90.805 ; 171.704,156.845 171.704,161.671 ; 171.958,119.126 171.958,123.952 ; 173.99,161.671 176.53,159.131 176.53,132.969 ; 174.117,128.524 174.117,133.35 ; 174.371,123.825 176.657,121.539 176.657,95.504 ; 174.498,90.551 174.498,95.377 ; 223.393,156.591 223.393,130.302 225.679,128.016 ; 223.647,118.745 223.647,92.456 225.933,90.17 ; 225.425,156.337 225.425,161.163 ; 225.806,118.364 225.806,123.19 ; 227.965,127.762 227.965,132.588 ; 227.965,161.036 230.505,158.496 230.505,132.334 ; 228.219,90.043 228.219,94.869 ; 228.219,123.19 230.505,120.904 230.505,94.869 ; 231.521,124.587 236.347,124.587 ; 231.648,126.873 234.061,129.286 260.223,129.286 ; 232.029,161.925 234.061,159.893 260.731,159.893 ; 232.029,164.338 236.855,164.338 ; 232.283,85.979 237.109,85.979 ; 232.41,88.392 234.696,90.678 260.731,90.678 ; 236.093,122.174 262.255,122.174 264.668,124.587 ; 236.22,166.878 262.89,166.878 265.049,164.719 ; 236.982,83.693 263.017,83.693 265.43,86.106 ; 260.223,162.179 265.049,162.179 ; 260.604,88.392 265.43,88.392 ; 267.081,156.337 267.081,130.302 269.367,128.016 ; 267.208,118.745 267.208,92.71 269.748,90.17 ; 269.367,156.21 269.367,161.036 ; 269.621,118.491 269.621,123.317 ; 271.653,161.036 274.193,158.496 274.193,132.334 ; 271.78,127.889 271.78,132.715 ; 272.034,123.19 274.32,120.904 274.32,94.869 ; 272.161,89.916 272.161,94.742 ; 289.179,156.845 289.179,130.556 291.465,128.27 ; 289.433,118.999 289.433,92.71 291.719,90.424 ; 291.211,156.591 291.211,161.417 ; 291.592,118.618 291.592,123.444 ; 293.751,128.016 293.751,132.842 ; 293.751,161.29 296.291,158.75 296.291,132.588 ; 294.005,90.297 294.005,95.123 ; 294.005,123.444 296.291,121.158 296.291,95.123 ; 297.307,124.841 302.133,124.841 ; 297.434,127.127 299.847,129.54 326.009,129.54 ; 297.815,162.179 299.847,160.147 326.517,160.147 ; 297.815,164.592 302.641,164.592 ; 298.069,86.233 302.895,86.233 ; 298.196,88.646 300.482,90.932 326.517,90.932 ; 301.879,122.428 328.041,122.428 330.454,124.841 ; 302.006,167.132 328.676,167.132 330.835,164.973 ; 302.768,83.947 328.803,83.947 331.216,86.36 ; 326.009,162.433 330.835,162.433 ; 326.39,88.646 331.216,88.646 ; 332.867,156.591 332.867,130.556 335.153,128.27 ; 332.994,118.999 332.994,92.964 335.534,90.424 ; 335.153,156.464 335.153,161.29 ; 335.407,118.745 335.407,123.571 ; 337.439,161.29 339.979,158.75 339.979,132.588 ; 337.566,128.143 337.566,132.969 ; 337.82,123.444 340.106,121.158 340.106,95.123 ; 337.947,90.17 337.947,94.996
  Bottom Layer w3.048: 63.627,132.715 63.627,155.956 ; 63.881,94.869 63.881,118.11 ; 73.406,125.73 96.647,125.73 ; 73.66,163.195 96.901,163.195 ; 74.295,87.249 97.536,87.249 ; 107.569,132.588 107.569,155.829 ; 107.696,94.742 107.696,117.983 ; 129.032,133.35 129.032,156.591 ; 129.286,95.504 129.286,118.745 ; 138.811,126.365 162.052,126.365 ; 139.065,163.83 162.306,163.83 ; 139.7,87.884 162.941,87.884 ; 172.974,133.223 172.974,156.464 ; 173.101,95.377 173.101,118.618 ; 226.695,132.715 226.695,155.956 ; 226.949,94.869 226.949,118.11 ; 236.474,125.73 259.715,125.73 ; 236.728,163.195 259.969,163.195 ; 237.363,87.249 260.604,87.249 ; 270.637,132.588 270.637,155.829 ; 270.764,94.742 270.764,117.983 ; 292.481,132.969 292.481,156.21 ; 292.735,95.123 292.735,118.364 ; 302.26,125.984 325.501,125.984 ; 302.514,163.449 325.755,163.449 ; 303.149,87.503 326.39,87.503 ; 336.423,132.842 336.423,156.083 ; 336.55,94.996 336.55,118.237

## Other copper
Top Layer:
  region: 195.961,145.542
  region: 217.805,168.148
  region: 194.691,168.148
  region: 180.721,165.354
  region: 131.318,79.756
  region: 165.1,127.254
  region: 170.434,134.493
  region: 130.937,155.829
  region: 121.285,127.254
  region: 121.031,165.1
  region: 278.384,164.719
  region: 228.981,79.121
  region: 262.763,126.619
  region: 268.097,133.858
  region: 228.6,155.194
  region: 218.948,126.619
  region: 218.694,167.132
  region: 344.17,164.973
  region: 294.767,79.375
  region: 328.549,126.873
  region: 333.883,134.112
  region: 294.386,155.448
  region: 284.734,126.873
  region: 286.131,164.719
  region: 115.316,164.719
  region: 65.913,79.121
  region: 99.695,126.619
  region: 105.029,133.858
  region: 65.532,155.194
  region: 55.88,126.619
  region: 55.626,164.465
  text "f" at 185.674,171.577 h1.52
  text "f" at 349.123,171.196 h1.52
  text "f" at 120.269,170.942 h1.52
  text "f" at 283.337,170.942 h1.52
  text "a" at 184.531,169.418 h1.52
  text "a" at 347.98,169.037 h1.52
  text "a" at 119.126,168.783 h1.52
  text "a" at 282.194,168.783 h1.52
  text "b" at 184.658,167.513 h1.52
  text "b" at 348.107,167.132 h1.52
  text "b" at 119.253,166.878 h1.52
  text "b" at 282.321,166.878 h1.52
  text "c" at 185.801,165.481 h1.52
  text "c" at 349.25,165.1 h1.52
  text "c" at 120.396,164.846 h1.52
  text "c" at 283.464,164.846 h1.52
  text "g" at 116.84,125.349 h1.52
  text "g" at 280.289,124.968 h1.52
  text "g" at 51.435,124.714 h1.52
  text "g" at 214.503,124.714 h1.52
  text "e" at 116.967,122.301 h1.52
  text "e" at 280.416,121.92 h1.52
  text "e" at 51.562,121.666 h1.52
  text "e" at 214.63,121.666 h1.52
  text "d" at 117.221,119.888 h1.52
  text "d" at 280.67,119.507 h1.52
  text "d" at 51.816,119.253 h1.52
  text "d" at 214.884,119.253 h1.52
